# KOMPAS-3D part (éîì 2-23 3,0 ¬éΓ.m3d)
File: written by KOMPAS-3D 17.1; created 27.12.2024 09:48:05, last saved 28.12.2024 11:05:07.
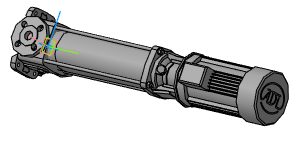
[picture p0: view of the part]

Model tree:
1. Операция без истории:4  (labels: ВМН 2-23 3,0 кВт)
